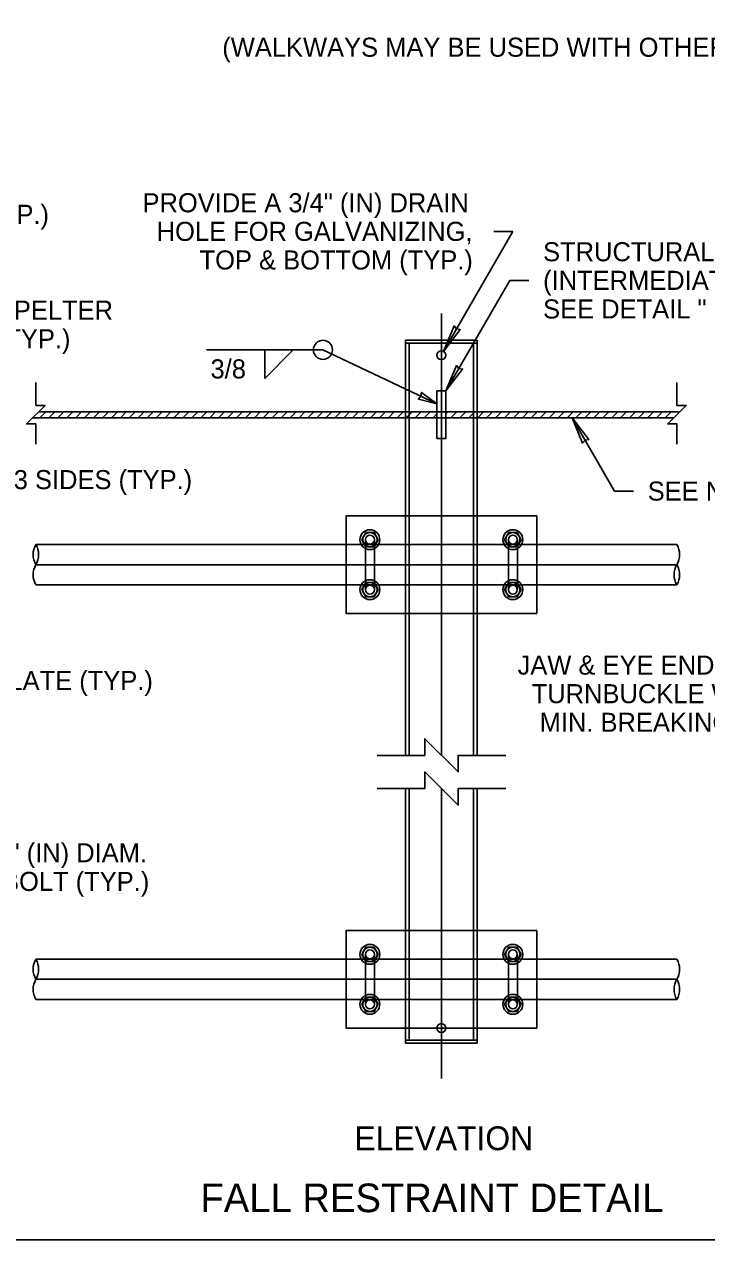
# Model space of a CAD drawing. Extents: x 99862 to 103151, y 100000 to 105076.
# Drawn here: x 100585 to 101158, y 100000 to 101019 of the extents above; entities that cross this region are included whole.
import ezdxf

# ---------------------------------------------------------------- set-up
doc = ezdxf.new("R2010")
doc.units = 0
for name, color, linetype in [('Level 1', 7, 'Continuous'), ('Level 15', 7, 'Continuous'), ('Level 20', 7, 'Continuous'), ('Level 36', 7, 'Continuous'), ('Level 4', 7, 'Continuous'), ('Level 6', 7, 'Continuous')]:
    doc.layers.add(name, color=color, linetype=linetype)

msp = doc.modelspace()

# ---------------------------------------------------------------- linework, layer by layer
at = {"layer": 'Level 1'}
msp.add_lwpolyline([(99862, 99999.5), (103151, 99999.5), (103151, 102075.5), (99862, 102075.5)], close=True, dxfattribs=at)
at = {"layer": 'Level 15'}
for p, q in [((100937, 100744.8), (100995.2, 100845.5)), ((100979.2, 100845.5), (100995.2, 100845.5)), ((100938.9, 100711.6), (100992.5, 100804.4)), ((100992.5, 100804.4), (101008.5, 100804.4)), ((100935.1, 100776.7), (100935.1, 100405.8)), ((100931.4, 100700.9), (100835.7, 100746.1)), ((101044.8, 100689.1), (101080.3, 100627.6)), ((101080.3, 100627.6), (101096.3, 100627.6)), ((100594.7, 100565.8), (101132.8, 100565.8)), ((100935.1, 100378), (100935.1, 100134.7)), ((100594.7, 100218), (101132.8, 100218))]:
    msp.add_line(p, q, dxfattribs=at)
for points in [[(100937, 100744.8), (100951, 100763.1), (100947.9, 100763.7), (100945.8, 100766.1)], [(100938.9, 100711.6), (100952.9, 100729.9), (100949.8, 100730.5), (100947.7, 100732.9)], [(100931.4, 100700.9), (100915.8, 100704.8), (100917.8, 100707.3), (100918.5, 100710.4)], [(101044.8, 100689.1), (101053.6, 100667.9), (101055.7, 100670.3), (101058.8, 100670.8)]]:
    msp.add_lwpolyline(points, close=True, dxfattribs=at)
for points in [[(100594.7, 100667), (100594.7, 100683.9), (100586.9, 100683.9), (100602.4, 100699.4), (100594.7, 100699.4), (100594.7, 100718.7)], [(101132.8, 100667), (101132.8, 100683.9), (101125.1, 100683.9), (101140.6, 100699.4), (101132.8, 100699.4), (101132.8, 100718.7)], [(100881.2, 100405.8), (100921.2, 100405.8), (100921.2, 100419.8), (100949.1, 100391.9), (100949.1, 100405.8), (100989.1, 100405.8)], [(100881.2, 100378), (100921.2, 100378), (100921.2, 100391.9), (100949.1, 100364), (100949.1, 100378), (100989.1, 100378)]]:
    msp.add_lwpolyline(points, dxfattribs=at)
for centre, start, end in [((100609.3, 100574.3), 150, 210), ((100580.1, 100574.3), 330, 30), ((101118.2, 100574.3), 330, 30), ((100609.3, 100557.4), 150, 210), ((101147.4, 100557.4), 150, 210), ((101118.2, 100557.4), 330, 30), ((100609.3, 100226.4), 150, 210), ((100580.1, 100226.4), 330, 30), ((101118.2, 100226.4), 330, 30), ((100609.3, 100209.5), 150, 210), ((101147.4, 100209.5), 150, 210), ((101118.2, 100209.5), 330, 30)]:
    msp.add_arc(centre, 16.9, start, end, dxfattribs=at)
at = {"layer": 'Level 20'}
msp.add_line((100737.9, 100746.1), (100835.7, 100746.1), dxfattribs=at)
msp.add_lwpolyline([(100786.8, 100746.1), (100810.8, 100746.1), (100786.8, 100722.1)], close=True, dxfattribs=at)
msp.add_circle((100835.7, 100746.1), 8, dxfattribs=at)
at = {"layer": 'Level 36'}
for p, q in [((100908.2, 100751.6), (100908.2, 100405.8)), ((100962, 100751.6), (100962, 100405.8)), ((100931.4, 100694.1), (100938.9, 100694.1)), ((100931.4, 100689.1), (100938.9, 100689.1)), ((100905.1, 100606.8), (100965.1, 100606.8)), ((100871.4, 100544.9), (100871.4, 100586.8)), ((100878.9, 100544.9), (100878.9, 100586.8)), ((100991.4, 100544.9), (100991.4, 100586.8)), ((100998.9, 100544.9), (100998.9, 100586.8)), ((100855.1, 100582.7), (101015.1, 100582.7)), ((100855.1, 100549), (101015.1, 100549)), ((100905.1, 100524.9), (100965.1, 100524.9)), ((100908.2, 100378), (100908.2, 100167)), ((100962, 100378), (100962, 100167)), ((100905.1, 100258.9), (100965.1, 100258.9)), ((100871.4, 100238.9), (100871.4, 100197)), ((100878.9, 100238.9), (100878.9, 100197)), ((100991.4, 100238.9), (100991.4, 100197)), ((100998.9, 100238.9), (100998.9, 100197)), ((100855.1, 100234.8), (101015.1, 100234.8)), ((100855.1, 100201.1), (101015.1, 100201.1)), ((100905.1, 100177), (100965.1, 100177))]:
    msp.add_line(p, q, dxfattribs=at)
at = {"layer": 'Level 4'}
for p, q in [((100931.4, 100689.1), (100592.2, 100689.1)), ((100931.4, 100694.1), (100597.2, 100694.1)), ((100598.1, 100689.1), (100603.1, 100694.1)), ((100605.6, 100689.1), (100610.6, 100694.1)), ((100613.1, 100689.1), (100618.1, 100694.1)), ((100620.6, 100689.1), (100625.6, 100694.1)), ((100628.1, 100689.1), (100633.1, 100694.1)), ((100635.6, 100689.1), (100640.6, 100694.1)), ((100643.1, 100689.1), (100648.1, 100694.1)), ((100650.6, 100689.1), (100655.6, 100694.1)), ((100658.1, 100689.1), (100663.1, 100694.1)), ((100665.6, 100689.1), (100670.6, 100694.1)), ((100673.1, 100689.1), (100678.1, 100694.1)), ((100680.6, 100689.1), (100685.6, 100694.1)), ((100688.1, 100689.1), (100693.1, 100694.1)), ((100695.6, 100689.1), (100700.6, 100694.1)), ((100703.1, 100689.1), (100708.1, 100694.1)), ((100710.6, 100689.1), (100715.6, 100694.1)), ((100718.1, 100689.1), (100723.1, 100694.1)), ((100725.6, 100689.1), (100730.6, 100694.1)), ((100733.1, 100689.1), (100738.1, 100694.1)), ((100740.6, 100689.1), (100745.6, 100694.1)), ((100748.1, 100689.1), (100753.1, 100694.1)), ((100755.6, 100689.1), (100760.6, 100694.1)), ((100763.1, 100689.1), (100768.1, 100694.1)), ((100770.6, 100689.1), (100775.6, 100694.1)), ((100778.1, 100689.1), (100783.1, 100694.1)), ((100785.6, 100689.1), (100790.6, 100694.1)), ((100793.1, 100689.1), (100798.1, 100694.1)), ((100800.6, 100689.1), (100805.6, 100694.1)), ((100808.1, 100689.1), (100813.1, 100694.1)), ((100815.6, 100689.1), (100820.6, 100694.1)), ((100823.1, 100689.1), (100828.1, 100694.1)), ((100830.6, 100689.1), (100835.6, 100694.1)), ((100838.1, 100689.1), (100843.1, 100694.1)), ((100845.6, 100689.1), (100850.6, 100694.1)), ((100853.1, 100689.1), (100858.1, 100694.1)), ((100860.6, 100689.1), (100865.6, 100694.1)), ((100868.1, 100689.1), (100873.1, 100694.1)), ((100875.6, 100689.1), (100880.6, 100694.1)), ((100883.1, 100689.1), (100888.1, 100694.1)), ((100890.6, 100689.1), (100895.6, 100694.1)), ((100898.1, 100689.1), (100903.1, 100694.1)), ((100905.6, 100689.1), (100910.6, 100694.1)), ((100913.1, 100689.1), (100918.1, 100694.1)), ((100920.6, 100689.1), (100925.6, 100694.1)), ((100928.1, 100689.1), (100931.4, 100692.4)), ((100938.9, 100692.4), (100940.6, 100694.1)), ((101135.3, 100694.1), (100938.9, 100694.1)), ((101130.3, 100689.1), (100938.9, 100689.1)), ((100943.1, 100689.1), (100948.1, 100694.1)), ((100950.6, 100689.1), (100955.6, 100694.1)), ((100958.1, 100689.1), (100963.1, 100694.1)), ((100965.6, 100689.1), (100970.6, 100694.1)), ((100973.1, 100689.1), (100978.1, 100694.1)), ((100980.6, 100689.1), (100985.6, 100694.1)), ((100988.1, 100689.1), (100993.1, 100694.1)), ((100995.6, 100689.1), (101000.6, 100694.1)), ((101003.1, 100689.1), (101008.1, 100694.1)), ((101010.6, 100689.1), (101015.6, 100694.1)), ((101018.1, 100689.1), (101023.1, 100694.1)), ((101025.6, 100689.1), (101030.6, 100694.1)), ((101033.1, 100689.1), (101038.1, 100694.1)), ((101040.6, 100689.1), (101045.6, 100694.1)), ((101048.1, 100689.1), (101053.1, 100694.1)), ((101055.6, 100689.1), (101060.6, 100694.1)), ((101063.1, 100689.1), (101068.1, 100694.1)), ((101070.6, 100689.1), (101075.6, 100694.1)), ((101078.1, 100689.1), (101083.1, 100694.1)), ((101085.6, 100689.1), (101090.6, 100694.1)), ((101093.1, 100689.1), (101098.1, 100694.1)), ((101100.6, 100689.1), (101105.6, 100694.1)), ((101108.1, 100689.1), (101113.1, 100694.1)), ((101115.6, 100689.1), (101120.6, 100694.1)), ((101123.1, 100689.1), (101128.1, 100694.1))]:
    msp.add_line(p, q, dxfattribs=at)
for points in [[(100931.4, 100711.6), (100938.9, 100711.6), (100938.9, 100671.6), (100931.4, 100671.6)], [(100882.1, 100586.8), (100878.6, 100580.8), (100871.7, 100580.8), (100868.2, 100586.8), (100871.7, 100592.8), (100878.6, 100592.8)], [(101002.1, 100586.8), (100998.6, 100580.8), (100991.7, 100580.8), (100988.2, 100586.8), (100991.7, 100592.8), (100998.6, 100592.8)], [(100882.1, 100544.9), (100878.6, 100538.9), (100871.7, 100538.9), (100868.2, 100544.9), (100871.7, 100550.9), (100878.6, 100550.9)], [(101002.1, 100544.9), (100998.6, 100538.9), (100991.7, 100538.9), (100988.2, 100544.9), (100991.7, 100550.9), (100998.6, 100550.9)], [(100882.1, 100238.9), (100878.6, 100232.9), (100871.7, 100232.9), (100868.2, 100238.9), (100871.7, 100244.9), (100878.6, 100244.9)], [(101002.1, 100238.9), (100998.6, 100232.9), (100991.7, 100232.9), (100988.2, 100238.9), (100991.7, 100244.9), (100998.6, 100244.9)], [(100882.1, 100197), (100878.6, 100191), (100871.7, 100191), (100868.2, 100197), (100871.7, 100203), (100878.6, 100203)], [(101002.1, 100197), (100998.6, 100191), (100991.7, 100191), (100988.2, 100197), (100991.7, 100203), (100998.6, 100203)]]:
    msp.add_lwpolyline(points, close=True, dxfattribs=at)
at = {"layer": 'Level 6'}
for p, q in [((100594.7, 100582.7), (100855.1, 100582.7)), ((101132.8, 100582.7), (101015.1, 100582.7)), ((100594.7, 100549), (100855.1, 100549)), ((101132.8, 100549), (101015.1, 100549)), ((100594.7, 100234.8), (100855.1, 100234.8)), ((101132.8, 100234.8), (101015.1, 100234.8)), ((100594.7, 100201.1), (100855.1, 100201.1)), ((101132.8, 100201.1), (101015.1, 100201.1))]:
    msp.add_line(p, q, dxfattribs=at)
for points in [[(100905.1, 100751.6), (100965.1, 100751.6), (100965.1, 100754.1), (100905.1, 100754.1)], [(100905.1, 100164.5), (100965.1, 100164.5), (100965.1, 100167), (100905.1, 100167)]]:
    msp.add_lwpolyline(points, close=True, dxfattribs=at)
for points in [[(100905.1, 100606.8), (100905.1, 100751.6), (100965.1, 100751.6), (100965.1, 100606.8)], [(100905.1, 100524.9), (100855.1, 100524.9), (100855.1, 100606.8), (100905.1, 100606.8)], [(100905.1, 100405.8), (100905.1, 100606.8)], [(100965.1, 100606.8), (101015.1, 100606.8), (101015.1, 100524.9), (100965.1, 100524.9)], [(100965.1, 100606.8), (100965.1, 100405.8)], [(100905.1, 100177), (100905.1, 100378)], [(100965.1, 100378), (100965.1, 100177)], [(100905.1, 100258.9), (100855.1, 100258.9), (100855.1, 100177), (100905.1, 100177)], [(100965.1, 100177), (101015.1, 100177), (101015.1, 100258.9), (100965.1, 100258.9)], [(100905.1, 100177), (100905.1, 100167), (100965.1, 100167), (100965.1, 100177)]]:
    msp.add_lwpolyline(points, dxfattribs=at)
for centre, radius in [((100935.1, 100741.6), 3.75), ((100875.1, 100586.8), 8.35), ((100995.1, 100586.8), 8.35), ((100875.1, 100586.8), 5.99), ((100875.1, 100586.8), 3.75), ((100995.1, 100586.8), 5.99), ((100995.1, 100586.8), 3.75), ((100875.1, 100544.9), 8.35), ((100875.1, 100544.9), 5.99), ((100875.1, 100544.9), 3.75), ((100995.1, 100544.9), 8.35), ((100995.1, 100544.9), 5.99), ((100995.1, 100544.9), 3.75), ((100875.1, 100238.9), 8.35), ((100875.1, 100238.9), 5.99), ((100875.1, 100238.9), 3.75), ((100995.1, 100238.9), 8.35), ((100995.1, 100238.9), 5.99), ((100995.1, 100238.9), 3.75), ((100875.1, 100197), 8.35), ((100875.1, 100197), 5.99), ((100875.1, 100197), 3.75), ((100995.1, 100197), 8.35), ((100995.1, 100197), 5.99), ((100995.1, 100197), 3.75), ((100935.1, 100177), 3.75)]:
    msp.add_circle(centre, radius, dxfattribs=at)

# ---------------------------------------------------------------- texts
at = {"layer": 'Level 20'}
for s, height, p in [('(WALKWAYS MAY BE USED WITH OTHER LAYOUTS THAN THAT SHOWN ABOVE)', 16, (100751.2, 100992)), ('PROVIDE A 3/4" (IN) DRAIN', 16, (100684.2, 100861.5)), ('(TYP.)', 16, (100543.9, 100851.8)), ('HOLE FOR GALVANIZING,', 16, (100696.1, 100837.5)), ('TOP & BOTTOM (TYP.)', 16, (100732.1, 100813.5)), ('STRUCTURAL LUG', 16, (101020.5, 100820.4)), ('(INTERMEDIATE SUPPORT)', 16, (101020.5, 100796.4)), ('SEE DETAIL "', 16, (101020.5, 100772.4)), ('CLOSED SPELTER', 16, (100468, 100771.4)), ('SOCKET (TYP.)', 16, (100468, 100747.4)), ('3/8', 16, (100741.3, 100722.1)), ('3 SIDES (TYP.)', 16, (100576.1, 100629.2)), ('SEE NOTE 4', 16, (101108.3, 100619.6)), ('JAW & EYE END OPEN BODY', 16, (100999.1, 100473.6)), ('3/4" (IN) PLATE (TYP.)', 16, (100472.5, 100460.6)), ('TURNBUCKLE WITH 14 KIPS', 16, (101010.9, 100449.6)), ('MIN. BREAKING STRENGTH', 16, (101017.6, 100425.6)), ('3/4" (IN) DIAM.', 16, (100543.7, 100316.1)), ('U-BOLT (TYP.)', 16, (100543.7, 100292.1)), (' ELEVATION', 20, (100854.6, 100074.6)), ('FALL RESTRAINT DETAIL', 24, (100732.8, 100022.6))]:
    msp.add_text(s, height=height, dxfattribs=at).set_placement(p)

doc.saveas('drawing.dxf')
